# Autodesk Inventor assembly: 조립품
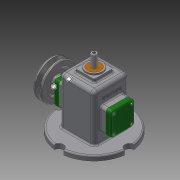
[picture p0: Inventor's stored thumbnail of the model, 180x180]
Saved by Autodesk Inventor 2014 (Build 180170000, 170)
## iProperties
Created: 2018-07
Part Number: 조립품
Document SubType Name: Assembly
Designer: kh
Author: kh
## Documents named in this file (16)
- C:\Users\kh\Desktop\480707V1020\조립품.iam
- C:\Users\kh\Desktop\480707V1020\본체.ipt
- C:\Users\kh\Desktop\480707V1020\앞커버.ipt
- C:\Users\kh\Desktop\480707V1020\뒤커버.ipt
- C:\Users\kh\Desktop\480707V1020\편심축.ipt
- C:\Users\kh\Desktop\480707V1020\베어링 12x32x10.ipt
- C:\Users\kh\Desktop\480707V1020\오일 실 12 25 7.ipt
- C:\Users\kh\Desktop\480707V1020\키 4x4x10.ipt
- C:\Users\kh\Desktop\480707V1020\V벨트풀리.ipt
- C:\Users\kh\Desktop\480707V1020\링크.ipt
- C:\Users\kh\Desktop\480707V1020\슬라이드.ipt
- C:\Users\kh\Desktop\480707V1020\부시.ipt
- C:\Users\kh\Desktop\480707V1020\핀 5x18.ipt
- C:\Users\kh\Desktop\480707V1020\고정핀 1.2x8.ipt
- C:\Users\kh\Desktop\480707V1020\볼트 M4.ipt
- C:\Users\kh\Desktop\480707V1020\멈춤나사 M3x8.ipt
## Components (3 placed, 3 different names)
1. V벨트풀리:1 — 플러쉬:1
2. 핀 5x18:1
3. 고정핀 1.2x8:1 — 각도:2
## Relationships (2: Flush 1, Angle 1)
- 플러쉬:1 [Flush]: V벨트풀리:1
- 각도:2 [Angle]: 고정핀 1.2x8:1
